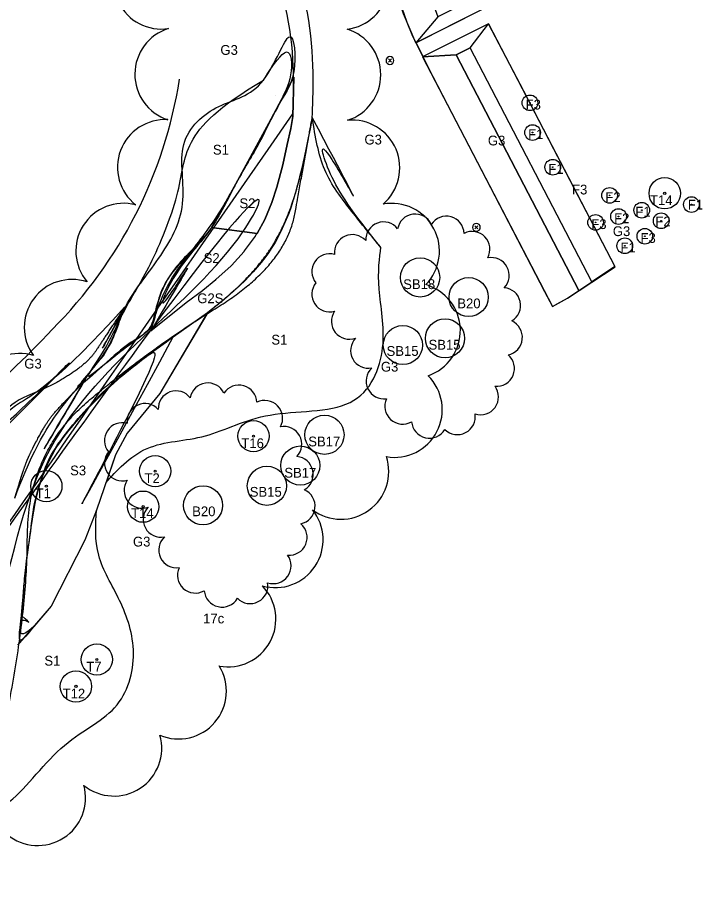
# Model space of a CAD drawing. Extents: x 0 to 512122, y 0 to 6212554.
# Drawn here: x 511674.6 to 511762.2, y 6211394.2 to 6211506.3 of the extents above; entities that cross this region are included whole.
import ezdxf

# ---------------------------------------------------------------- set-up
doc = ezdxf.new("R2010")
doc.units = 0
for name, color, linetype in [('_G3_engræsser', 7, 'Continuous'), ('_lights', 7, 'Continuous'), ('_ny fruit trees', 7, 'Continuous'), ('_Paths', 7, 'Continuous'), ('_S1_rabarber', 7, 'Continuous'), ('_S2_skovjorbær', 7, 'Continuous'), ('_S3_Mynte', 7, 'Continuous'), ('_S4_Løvstikke', 7, 'Continuous'), ('Clouds', 7, 'Continuous'), ('L40 jord udlagt muld og grøft', 7, 'Continuous'), ('Skel', 7, 'Continuous'), ('TV_U_AFM_Symbl_Gul', 7, 'Continuous'), ('TV_U_LYS_iWay', 7, 'Continuous'), ('TV_U_LYS_Mastenummer', 7, 'Continuous')]:
    doc.layers.add(name, color=color, linetype=linetype)

# ---------------------------------------------------------------- blocks, each defined once
blk = doc.blocks.new('SOLITAIRE TREES')
at = {"layer": 'Skel'}
for radius in [2, 0.141]:
    blk.add_circle((0, 0), radius, dxfattribs=at)

msp = doc.modelspace()

# ---------------------------------------------------------------- linework, layer by layer
at = {"layer": '_G3_engræsser'}
for centre, radius, start, end in [((511638.11, 6211507.41), 57.91, 315.0144, 351.0744), ((511598.66, 6211541.42), 109.92, 309.1647, 317.0116)]:
    msp.add_arc(centre, radius, start, end, dxfattribs=at)
at = {"layer": '_lights'}
for p, q in [((511722.42, 6211501), (511722.02, 6211500.61)), ((511722.02, 6211501), (511722.41, 6211500.6)), ((511733.47, 6211479.7), (511733.08, 6211479.31)), ((511733.08, 6211479.7), (511733.47, 6211479.3))]:
    msp.add_line(p, q, dxfattribs=at)
for centre, start, end in [((511722.22, 6211500.8), 315.5636, 315), ((511722.22, 6211500.8), 315, 315.5636), ((511733.27, 6211479.5), 315.5636, 315), ((511733.27, 6211479.5), 315, 315.5636)]:
    msp.add_arc(centre, 0.5, start, end, dxfattribs=at)
at = {"layer": '_ny fruit trees'}
for centre, radius in [((511740.12, 6211495.4), 1), ((511740.12, 6211495.4), 0.0426), ((511740.45, 6211491.61), 1), ((511740.45, 6211491.61), 0.0426), ((511743.03, 6211487.18), 1), ((511743.03, 6211487.18), 0.0426), ((511750.3, 6211483.58), 1), ((511750.3, 6211483.58), 0.0426), ((511760.76, 6211482.41), 1), ((511751.44, 6211480.88), 1), ((511754.41, 6211481.69), 1), ((511760.76, 6211482.41), 0.0426), ((511748.51, 6211480.13), 1), ((511751.44, 6211480.88), 0.0426), ((511754.41, 6211481.69), 0.0426), ((511756.89, 6211480.33), 1), ((511748.51, 6211480.13), 0.0426), ((511756.89, 6211480.33), 0.0426), ((511754.8, 6211478.36), 1), ((511754.8, 6211478.36), 0.0426), ((511752.24, 6211477.14), 1), ((511752.24, 6211477.14), 0.0426)]:
    msp.add_circle(centre, radius, dxfattribs=at)
at = {"layer": '_Paths'}
for points, degree in [([(511709.79, 6211493.65), (511709.91, 6211496.22), (511710.39, 6211506.9), (511703.25, 6211521.64), (511712.2, 6211531.87), (511715.7, 6211532.9), (511716.19, 6211533.02)], 3), ([(511712.29, 6211493.53), (511712.41, 6211496.11), (511712.92, 6211507.42), (511706.22, 6211521.24), (511713.56, 6211529.63), (511716.31, 6211530.48), (511716.67, 6211530.57)], 3), ([(511640.46, 6211394.16), (511666, 6211408.81), (511672.52, 6211429.48), (511676.56, 6211451.28), (511690.48, 6211465.66), (511705.08, 6211478.47), (511709.82, 6211494.01), (511640.46, 6211394.16), (511709.82, 6211494.01)], 3), ([(511651.32, 6211395.4), (511670.02, 6211402.1), (511675.84, 6211429.41), (511675.93, 6211450.77), (511691.5, 6211463.95), (511708.9, 6211474.67), (511711.29, 6211488), (511712.29, 6211493.57)], 2)]:
    msp.add_open_spline(points, degree=degree, dxfattribs=at)
at = {"layer": '_S1_rabarber'}
for points in [[(511698.93, 6211468.63), (511692.8, 6211458.27), (511688.64, 6211453.21), (511687.14, 6211450.42), (511685.93, 6211446.9)], [(511698.93, 6211468.63), (511692.8, 6211458.27), (511688.64, 6211453.21), (511687.14, 6211450.42), (511685.93, 6211446.9)], [(511698.91, 6211468.6), (511692.8, 6211458.27), (511688.64, 6211453.21), (511687.14, 6211450.42), (511685.93, 6211446.9)], [(511684.72, 6211443.38), (511684.72, 6211443.38), (511683.23, 6211439.53), (511678.91, 6211431.1), (511674.62, 6211426.15)], [(511684.72, 6211443.38), (511683.23, 6211439.53), (511678.91, 6211431.1), (511674.62, 6211426.15)]]:
    msp.add_lwpolyline(points, dxfattribs=at)
for points in [[(511706.05, 6211498.31), (511704.37, 6211496.16), (511700.27, 6211495.63), (511694.55, 6211490.67), (511696.74, 6211482.28), (511692.83, 6211475.35), (511687.76, 6211469.33), (511687.18, 6211464.39), (511680.03, 6211456.87), (511686.7, 6211462.87), (511689.02, 6211464.94), (511692.19, 6211466.4), (511692.26, 6211469.95), (511694.51, 6211474.61), (511699.59, 6211478.82), (511702.45, 6211485.35), (511705.77, 6211490.39), (511707.8, 6211495.3), (511710.48, 6211498.52), (511709.77, 6211506.87), (511707.62, 6211500.33), (511706.05, 6211498.31)], [(511706.05, 6211498.31), (511700.24, 6211494.87), (511695.7, 6211490.19), (511695.7, 6211484.27), (511691.41, 6211473.85), (511688.35, 6211469.4), (511686.09, 6211464.02), (511682.39, 6211459.13), (511686.22, 6211462.43), (511690.08, 6211465.38), (511691.7, 6211466.48), (511692.37, 6211468.99), (511694.34, 6211473.6), (511699.41, 6211479.52), (511702.53, 6211485.09), (511705.92, 6211491.08), (511708.18, 6211495.52), (511709.84, 6211498.66), (511709.53, 6211503.61), (511706.05, 6211498.31), (511706.05, 6211498.31), (511706.05, 6211498.31)], [(511712.29, 6211493.53), (511710.77, 6211485.59), (511708.57, 6211476.81), (511702.2, 6211471.1), (511698.93, 6211468.63)], [(511712.29, 6211493.53), (511710.77, 6211485.59), (511708.57, 6211476.81), (511702.2, 6211471.1), (511698.93, 6211468.63)], [(511721.06, 6211476.91), (511717.29, 6211481.6), (511714.18, 6211486.23), (511712.29, 6211493.53), (511721.06, 6211476.91), (511712.29, 6211493.53)], [(511721.06, 6211476.91), (511719.8, 6211478.46), (511717.38, 6211481.45), (511713.41, 6211486.6), (511712.7, 6211491), (511712.29, 6211493.53)], [(511698.91, 6211468.6), (511699.31, 6211468.96), (511699.65, 6211469.22), (511700.54, 6211469.93), (511701.09, 6211470.38), (511702.16, 6211471.31), (511702.68, 6211471.79), (511703.7, 6211472.78), (511704.2, 6211473.29), (511704.91, 6211474.09), (511705.15, 6211474.36), (511705.6, 6211474.91), (511705.82, 6211475.19), (511706.26, 6211475.76), (511706.47, 6211476.06), (511706.78, 6211476.5), (511706.88, 6211476.65), (511707.03, 6211476.88), (511707.08, 6211476.96), (511707.17, 6211477.11), (511707.22, 6211477.19), (511707.46, 6211477.57), (511707.64, 6211477.89), (511707.99, 6211478.52), (511708.16, 6211478.84), (511708.64, 6211479.81), (511708.93, 6211480.46), (511709.46, 6211481.8), (511709.7, 6211482.47), (511710.15, 6211483.83), (511710.35, 6211484.52), (511710.73, 6211485.9), (511710.9, 6211486.6), (511711.1, 6211487.5), (511711.3, 6211488.46), (511711.39, 6211488.94)], [(511685.93, 6211446.9), (511687.21, 6211448.33), (511690.71, 6211452.25), (511698.77, 6211452.14), (511706.01, 6211456.38), (511718.64, 6211455.51), (511722.16, 6211464.4), (511720.44, 6211471.89), (511720.89, 6211475.75), (511721.06, 6211476.91)], [(511685.93, 6211446.9), (511687.21, 6211448.33), (511690.71, 6211452.25), (511698.77, 6211452.14), (511706.01, 6211456.38), (511718.64, 6211455.51), (511722.16, 6211464.4), (511720.44, 6211471.89), (511720.89, 6211475.75), (511721.06, 6211476.91)], [(511685.93, 6211446.9), (511687.21, 6211448.33), (511690.71, 6211452.25), (511698.77, 6211452.14), (511706.01, 6211456.38), (511718.64, 6211455.51), (511722.16, 6211464.4), (511720.44, 6211471.89), (511720.89, 6211475.75), (511721.06, 6211476.91)], [(511659.81, 6211399.94), (511668.56, 6211404.36), (511673.2, 6211404.11), (511679.92, 6211414.02), (511688.01, 6211417.39), (511690.19, 6211425.29), (511687.87, 6211432.03), (511684.34, 6211437.49), (511684.6, 6211441.59), (511684.72, 6211443.38)], [(511659.81, 6211399.94), (511668.56, 6211404.36), (511673.2, 6211404.11), (511679.92, 6211414.02), (511688.01, 6211417.39), (511690.19, 6211425.29), (511687.87, 6211432.03), (511684.34, 6211437.49), (511684.6, 6211441.59), (511684.72, 6211443.38)]]:
    msp.add_open_spline(points, degree=3, dxfattribs=at)
at = {"layer": '_S2_skovjorbær'}
for p, q in [((511703.63, 6211476.5), (511705.02, 6211478.38)), ((511703.63, 6211476.5), (511705.02, 6211478.38)), ((511703.63, 6211476.5), (511705.02, 6211478.38)), ((511701.98, 6211474.63), (511703.57, 6211476.43)), ((511701.98, 6211474.63), (511703.57, 6211476.43)), ((511701.98, 6211474.63), (511703.57, 6211476.43)), ((511699.99, 6211472.87), (511701.89, 6211474.54)), ((511699.99, 6211472.87), (511701.89, 6211474.54)), ((511699.99, 6211472.87), (511701.89, 6211474.54)), ((511698.31, 6211471.46), (511699.97, 6211472.85)), ((511698.31, 6211471.46), (511699.97, 6211472.85)), ((511698.31, 6211471.46), (511699.97, 6211472.85))]:
    msp.add_line(p, q, dxfattribs=at)
for points in [[(511705.24, 6211478.7), (511699.42, 6211479.47), (511702.54, 6211485.04), (511709.92, 6211498.68), (511709.79, 6211493.65), (511709.54, 6211492.14), (511709.08, 6211490.07), (511708.52, 6211487.49), (511707.78, 6211484.62), (511707.14, 6211482.68), (511706.21, 6211480.5), (511705.24, 6211478.7)], [(511705.24, 6211478.7), (511699.42, 6211479.47), (511702.54, 6211485.04), (511709.92, 6211498.68), (511709.79, 6211493.65), (511709.54, 6211492.14), (511709.08, 6211490.07), (511708.52, 6211487.49), (511707.78, 6211484.62), (511707.14, 6211482.68), (511706.21, 6211480.5), (511705.24, 6211478.7)], [(511705.14, 6211478.6), (511705.21, 6211478.7), (511699.42, 6211479.47)], [(511705.14, 6211478.6), (511705.21, 6211478.7), (511699.42, 6211479.47)], [(511705.14, 6211478.6), (511705.21, 6211478.7), (511699.42, 6211479.47)], [(511691.67, 6211466.29), (511696.19, 6211469.89), (511698.26, 6211471.42)], [(511691.67, 6211466.29), (511696.19, 6211469.89), (511698.26, 6211471.42)], [(511691.67, 6211466.29), (511696.19, 6211469.89), (511698.26, 6211471.42)]]:
    msp.add_lwpolyline(points, dxfattribs=at)
msp.add_lwpolyline([(511706.21, 6211480.5), (511707.14, 6211482.68), (511707.78, 6211484.62), (511708.52, 6211487.49), (511709.08, 6211490.07), (511709.54, 6211492.14), (511709.79, 6211493.65), (511709.92, 6211498.68), (511702.54, 6211485.04), (511699.42, 6211479.47), (511705.24, 6211478.7)], close=True, dxfattribs=at)
for centre, radius, start, end in [((511704.34, 6211478.88), 0.85, 323.4908, 340.3298), ((511704.34, 6211478.88), 0.85, 323.4908, 340.3298), ((511704.34, 6211478.88), 0.85, 323.4908, 340.3298), ((511702.82, 6211477.09), 1, 318.5109, 323.4908), ((511702.82, 6211477.09), 1, 318.5109, 323.4908), ((511702.82, 6211477.09), 1, 318.5109, 323.4908), ((511701.23, 6211475.29), 1, 311.2445, 318.5109), ((511701.23, 6211475.29), 1, 311.2445, 318.5109), ((511701.23, 6211475.29), 1, 311.2445, 318.5109), ((511699.33, 6211473.62), 1, 310.0415, 311.2445), ((511699.33, 6211473.62), 1, 310.0415, 311.2445), ((511699.33, 6211473.62), 1, 310.0415, 311.2445), ((511697.67, 6211472.22), 1, 306.5138, 310.0415), ((511697.67, 6211472.22), 1, 306.5138, 310.0415), ((511697.67, 6211472.22), 1, 306.5138, 310.0415)]:
    msp.add_arc(centre, radius, start, end, dxfattribs=at)
for points in [[(511699.42, 6211479.47), (511697.51, 6211476.99), (511694.06, 6211473.15), (511691.67, 6211466.29), (511699.42, 6211479.47), (511691.67, 6211466.29)], [(511699.42, 6211479.47), (511697.51, 6211476.99), (511694.06, 6211473.15), (511691.67, 6211466.29), (511699.42, 6211479.47), (511691.67, 6211466.29)], [(511699.42, 6211479.47), (511698.81, 6211478.63), (511697.2, 6211476.39), (511693.09, 6211472.94), (511692.19, 6211468.74), (511691.67, 6211466.29)]]:
    msp.add_open_spline(points, degree=3, dxfattribs=at)
at = {"layer": '_S3_Mynte'}
msp.add_lwpolyline([(511694.53, 6211465.5), (511698.91, 6211468.6), (511692.8, 6211458.27), (511688.64, 6211453.21), (511687.14, 6211450.42), (511684.72, 6211443.38), (511683.23, 6211439.53), (511678.91, 6211431.1), (511676.69, 6211428.53)], dxfattribs=at)
msp.add_lwpolyline([(511694.53, 6211465.5), (511698.91, 6211468.6), (511692.8, 6211458.27), (511688.64, 6211453.21), (511687.14, 6211450.42), (511684.72, 6211443.38), (511683.23, 6211439.53), (511678.91, 6211431.1), (511676.69, 6211428.53)], dxfattribs=at)
for points in [[(511675.11, 6211429.93), (511675.26, 6211431.43), (511675.43, 6211433.5), (511675.74, 6211436.7), (511676.19, 6211439.93), (511676.86, 6211444.5), (511677.63, 6211447.3), (511678.99, 6211450.53), (511680.7, 6211453.03), (511683.58, 6211456.41), (511687.43, 6211460.16), (511691.16, 6211463.08), (511694.53, 6211465.5), (511675.11, 6211429.93), (511694.53, 6211465.5)], [(511675.11, 6211429.93), (511675.16, 6211430.43), (511675.29, 6211431.62), (511675.45, 6211433.88), (511675.71, 6211436.72), (511676.29, 6211440.37), (511676.64, 6211443.96), (511677.64, 6211447.51), (511678.8, 6211450.46), (511680.95, 6211453.44), (511683.74, 6211456.68), (511687.2, 6211460.1), (511690.99, 6211462.98), (511693.4, 6211464.7), (511694.53, 6211465.5)], [(511676.69, 6211428.53), (511675.92, 6211427.55), (511674.64, 6211425.91), (511674.98, 6211428.55), (511675.07, 6211429.48), (511675.11, 6211429.93)], [(511676.69, 6211428.53), (511674.93, 6211426.87), (511674.96, 6211428.47), (511675.11, 6211429.93), (511676.69, 6211428.53), (511675.11, 6211429.93)]]:
    msp.add_open_spline(points, degree=3, dxfattribs=at)
at = {"layer": '_S4_Løvstikke'}
for points, degree in [([(511688.33, 6211469.33), (511679.63, 6211459.7), (511674.05, 6211456.91), (511671.46, 6211454.05), (511670.68, 6211451.52), (511688.33, 6211469.33), (511670.68, 6211451.52)], 3), ([(511688.28, 6211469.25), (511685.8, 6211465.49), (511683.31, 6211461.75), (511679.63, 6211459.7)], 2), ([(511683.58, 6211460.56), (511684.79, 6211462.18), (511685.56, 6211462.99), (511685.75, 6211463.29), (511685.91, 6211463.71), (511686.28, 6211464.27), (511686.72, 6211464.98), (511687.17, 6211466.22), (511687.64, 6211467.57), (511688.33, 6211469.33), (511683.58, 6211460.56), (511688.33, 6211469.33)], 3), ([(511687.39, 6211466.89), (511687.58, 6211467.42), (511687.75, 6211467.93), (511687.93, 6211468.42)], 2), ([(511687.93, 6211468.42), (511688.04, 6211468.7), (511688.15, 6211468.98), (511688.28, 6211469.25)], 2), ([(511686.98, 6211465.8), (511687.01, 6211465.89), (511687.05, 6211465.98), (511687.09, 6211466.08)], 2), ([(511687.09, 6211466.08), (511687.16, 6211466.26), (511687.23, 6211466.44), (511687.29, 6211466.62)], 2), ([(511687.29, 6211466.62), (511687.33, 6211466.71), (511687.36, 6211466.8), (511687.39, 6211466.89)], 2), ([(511686.58, 6211464.93), (511686.73, 6211465.23), (511686.86, 6211465.52), (511686.98, 6211465.8)], 2), ([(511685.88, 6211463.69), (511685.95, 6211463.8), (511686.02, 6211463.91), (511686.09, 6211464.02)], 2), ([(511686.09, 6211464.02), (511686.27, 6211464.33), (511686.44, 6211464.64), (511686.58, 6211464.93)], 2), ([(511684.95, 6211462.35), (511685.2, 6211462.68), (511685.44, 6211463.02), (511685.66, 6211463.36)], 2), ([(511685.66, 6211463.36), (511685.74, 6211463.47), (511685.81, 6211463.58), (511685.88, 6211463.69)], 2), ([(511683.71, 6211460.75), (511684.04, 6211461.25), (511684.38, 6211461.75), (511684.79, 6211462.18)], 2), ([(511684.79, 6211462.18), (511684.84, 6211462.22), (511684.88, 6211462.27), (511684.93, 6211462.31)], 2), ([(511684.93, 6211462.31), (511684.94, 6211462.32), (511684.94, 6211462.33), (511684.95, 6211462.35)], 2), ([(511674.26, 6211444.91), (511676.69, 6211451.49), (511680.72, 6211457.31), (511683.18, 6211459.96), (511683.58, 6211460.56), (511674.26, 6211444.91), (511683.58, 6211460.56)], 3), ([(511682.63, 6211459.46), (511682.87, 6211459.75), (511683.26, 6211460.2), (511683.71, 6211460.75)], 2), ([(511679.63, 6211459.7), (511677.85, 6211458.7), (511674.52, 6211457.74), (511671.37, 6211454.53), (511670.88, 6211452.39), (511670.68, 6211451.52)], 3), ([(511682.68, 6211459.37), (511682.54, 6211459.25), (511682.45, 6211459.17), (511682.41, 6211459.14)], 2), ([(511682.45, 6211459.07), (511682.59, 6211459.22), (511682.72, 6211459.37), (511682.85, 6211459.53)], 2), ([(511682.53, 6211459.33), (511682.56, 6211459.37), (511682.59, 6211459.41), (511682.63, 6211459.46)], 2), ([(511682.85, 6211459.53), (511682.79, 6211459.47), (511682.73, 6211459.42), (511682.68, 6211459.37)], 2), ([(511681.27, 6211457.86), (511681.65, 6211458.27), (511682.05, 6211458.67), (511682.45, 6211459.07)], 2), ([(511682.39, 6211459.13), (511682.38, 6211459.14), (511682.39, 6211459.15), (511682.4, 6211459.16)], 2), ([(511682.41, 6211459.14), (511682.4, 6211459.13), (511682.39, 6211459.13), (511682.39, 6211459.13)], 2), ([(511682.4, 6211459.16), (511682.42, 6211459.19), (511682.46, 6211459.25), (511682.53, 6211459.33)], 2), ([(511677.07, 6211452.25), (511678.05, 6211454.09), (511679.27, 6211455.8), (511680.72, 6211457.31)], 2), ([(511680.72, 6211457.31), (511680.9, 6211457.49), (511681.08, 6211457.67), (511681.27, 6211457.86)], 2), ([(511676.56, 6211451.28), (511676.7, 6211451.57), (511676.85, 6211451.85), (511677, 6211452.13)], 2), ([(511677, 6211452.13), (511677.03, 6211452.17), (511677.05, 6211452.21), (511677.07, 6211452.25)], 2), ([(511675.34, 6211448.35), (511675.68, 6211449.35), (511676.09, 6211450.33), (511676.56, 6211451.28)], 2), ([(511675.01, 6211447.33), (511675.11, 6211447.67), (511675.22, 6211448.01), (511675.34, 6211448.35)], 2), ([(511674.79, 6211446.58), (511674.86, 6211446.83), (511674.93, 6211447.08), (511675.01, 6211447.33)], 2), ([(511674.26, 6211444.91), (511674.44, 6211445.47), (511674.61, 6211446.02), (511674.79, 6211446.58)], 2)]:
    msp.add_open_spline(points, degree=degree, dxfattribs=at)
at = {"layer": 'Clouds'}
for centre, radius, start, end in [((511715.99, 6211510.86), 6.1, 277.3369, 62.3369), ((511693.01, 6211510.92), 6.1, 133.6048, 278.6048), ((511695.71, 6211499.05), 6.1, 107.0668, 252.0668), ((511714.95, 6211498.98), 6.1, 287.6654, 72.6654), ((511693.49, 6211487.16), 6.1, 86.7882, 231.7882), ((511717.38, 6211487.1), 6.1, 310.4337, 95.4337), ((511688.17, 6211476.47), 6.1, 75.2403, 220.2403), ((511722.45, 6211476.46), 6.1, 315.4622, 100.4622), ((511725.45, 6211478.91), 2.28, 25.2077, 170.2077), ((511729.42, 6211478.64), 2.28, 2.0157, 147.0157), ((511721.4, 6211477.91), 2.28, 37.6761, 182.6761), ((511717.41, 6211476.29), 2.28, 41.3523, 186.3523), ((511732.72, 6211476.69), 2.28, 331.608, 116.608), ((511714.52, 6211473.85), 2.28, 74.1952, 219.1952), ((511735.18, 6211473.36), 2.28, 316.3178, 101.3178), ((511681.57, 6211466.74), 6.1, 71.4274, 216.4274), ((511714.52, 6211470.97), 2.28, 140.8408, 285.8408), ((511725.12, 6211466.31), 6.1, 289.0782, 74.0782), ((511736.64, 6211469.52), 2.28, 300.1916, 85.1916), ((511717.02, 6211467.49), 2.28, 145.6596, 290.6596), ((511736.87, 6211465.45), 2.28, 281.4375, 66.4375), ((511719.47, 6211463.77), 2.28, 135.9748, 280.9748), ((511674.86, 6211457.29), 6.1, 72.8126, 217.8126), ((511735.85, 6211461.47), 2.28, 264.8625, 49.8625), ((511721.46, 6211459.86), 2.28, 133.096, 278.096), ((511722.81, 6211456.22), 6.1, 260.1447, 45.1447), ((511698.94, 6211457.34), 2.28, 25.2077, 170.2077), ((511702.92, 6211457.07), 2.28, 2.0157, 147.0157), ((511694.89, 6211456.33), 2.28, 37.6761, 182.6761), ((511733.82, 6211457.84), 2.28, 251.5454, 36.5454), ((511706.22, 6211455.11), 2.28, 331.608, 116.608), ((511723.85, 6211456.64), 2.28, 154.9974, 299.9974), ((511690.9, 6211454.72), 2.28, 41.3523, 186.3523), ((511730.85, 6211455.3), 2.28, 224.7551, 9.7551), ((511688.01, 6211452.27), 2.28, 74.1952, 219.1952), ((511708.67, 6211451.79), 2.28, 316.3178, 101.3178), ((511727.26, 6211454.85), 2.28, 184.528, 329.528), ((511688.01, 6211449.39), 2.28, 140.8408, 285.8408), ((511710.13, 6211447.94), 2.28, 300.1916, 85.1916), ((511715.97, 6211448.31), 6.1, 233.2004, 18.2004), ((511690.52, 6211445.91), 2.28, 145.6596, 290.6596), ((511710.37, 6211443.88), 2.28, 281.4375, 66.4375), ((511692.96, 6211442.19), 2.28, 135.9748, 280.9748), ((511707.58, 6211439.58), 6.1, 254.071, 39.071), ((511709.35, 6211439.9), 2.28, 264.8625, 49.8625), ((511694.95, 6211438.29), 2.28, 133.096, 278.096), ((511707.31, 6211436.27), 2.28, 251.5454, 36.5454), ((511697.34, 6211435.06), 2.28, 154.9974, 299.9974), ((511701.54, 6211429.46), 6.1, 259.1824, 44.1824), ((511704.34, 6211433.72), 2.28, 224.7551, 9.7551), ((511700.76, 6211433.27), 2.28, 184.528, 329.528), ((511695.21, 6211420.25), 6.1, 246.8826, 31.8826), ((511686.95, 6211412.96), 6.1, 230.9058, 15.9058), ((511677.21, 6211406.64), 6.1, 230.1332, 15.1332)]:
    msp.add_arc(centre, radius, start, end, dxfattribs=at)
at = {"layer": 'L40 jord udlagt muld og grøft'}
for points in [[(511719.84, 6211532.64), (511724, 6211531.81), (511724.74, 6211524.88), (511725.4, 6211516.61), (511726.74, 6211510.85), (511728.35, 6211506.39), (511725.51, 6211503.06), (511723.96, 6211506.78), (511722.52, 6211511.27), (511721.38, 6211516.76), (511720.92, 6211521.34), (511720.67, 6211526.89), (511720.3, 6211530.04), (511719.84, 6211532.64)], [(511723.4, 6211508.54), (511724.37, 6211505.7), (511725.03, 6211504.14), (511727.06, 6211500), (511729.53, 6211495.25), (511735.07, 6211484.6), (511741.98, 6211471.32), (511742.99, 6211469.39), (511743.97, 6211469.93), (511744.93, 6211470.46), (511750.99, 6211474.45), (511743.16, 6211489.5), (511739.32, 6211496.88), (511734.83, 6211505.51), (511726.47, 6211501.3), (511725.59, 6211503.1), (511733.95, 6211507.31)], [(511732.49, 6211502.43), (511734.83, 6211505.51), (511750.97, 6211474.49), (511748.04, 6211472.54), (511732.49, 6211502.43)], [(511726.4, 6211501.27), (511742.99, 6211469.39), (511744.93, 6211470.46), (511746.37, 6211471.42), (511730.7, 6211501.53), (511726.4, 6211501.27)]]:
    msp.add_lwpolyline(points, dxfattribs=at)
for points in [[(511725.51, 6211503.06), (511733.95, 6211507.31), (511730.13, 6211507.29), (511728.35, 6211506.39)], [(511726.4, 6211501.27), (511730.7, 6211501.53), (511732.49, 6211502.43), (511734.83, 6211505.51)], [(511730.7, 6211501.53), (511746.37, 6211471.42), (511748.04, 6211472.54), (511732.49, 6211502.43)]]:
    msp.add_lwpolyline(points, close=True, dxfattribs=at)
at = {"layer": 'TV_U_LYS_iWay'}
msp.add_arc((511709.92, 6211499.22), 3.69, 232.0045, 232.0219, dxfattribs=at)
at = {"layer": 'TV_U_LYS_Mastenummer'}
for centre in [(511726.08, 6211473.1), (511732.28, 6211470.59), (511732.28, 6211470.59), (511729.26, 6211465.32), (511723.87, 6211464.46), (511713.85, 6211453), (511713.85, 6211453), (511710.76, 6211449.07), (511710.76, 6211449.07), (511706.49, 6211446.49), (511706.49, 6211446.49), (511698.33, 6211443.99)]:
    msp.add_circle(centre, 2.5, dxfattribs=at)

# ---------------------------------------------------------------- block references
at = {"layer": 'Skel'}
for p in [(511757.34, 6211483.85), (511704.78, 6211452.83), (511692.21, 6211448.36), (511678.3, 6211446.44), (511690.67, 6211443.82), (511684.76, 6211424.3), (511682.08, 6211420.86)]:
    msp.add_blockref('SOLITAIRE TREES', p, dxfattribs=at)

# ---------------------------------------------------------------- texts
at = {"layer": 'TV_U_AFM_Symbl_Gul'}
for s, p in [('G3', (511700.55, 6211501.53)), ('F3', (511739.57, 6211494.55)), ('F1', (511739.89, 6211490.76)), ('G3', (511718.96, 6211490.08)), ('G3', (511734.74, 6211489.96)), ('S1', (511699.59, 6211488.79)), ('F1', (511742.47, 6211486.33)), ('F3', (511745.5, 6211483.7)), ('S2', (511702.98, 6211481.95)), ('F2', (511749.75, 6211482.73)), ('T14', (511755.46, 6211482.33)), ('F1', (511760.3, 6211481.77)), ('F1', (511753.58, 6211480.87)), ('F2', (511750.88, 6211480.03)), ('F2', (511756.15, 6211479.62)), ('F3', (511747.96, 6211479.28)), ('G3', (511750.71, 6211478.38)), ('F3', (511754.25, 6211477.51)), ('F1', (511751.69, 6211476.29)), ('S2', (511698.41, 6211474.95)), ('SB18', (511723.91, 6211471.61)), ('G2S', (511697.59, 6211469.81)), ('B20', (511730.83, 6211469.16)), ('S1', (511707.06, 6211464.52)), ('SB15', (511727.15, 6211463.88)), ('SB15', (511721.79, 6211463.08)), ('G3', (511675.48, 6211461.46)), ('G3', (511721.06, 6211461.07)), ('SB17', (511711.78, 6211451.52)), ('T16', (511703.23, 6211451.3)), ('S3', (511681.34, 6211447.82)), ('SB17', (511708.72, 6211447.53)), ('T2', (511690.85, 6211446.83)), ('T1', (511676.94, 6211444.9)), ('SB15', (511704.3, 6211445.09)), ('B20', (511696.94, 6211442.6)), ('T14', (511689.14, 6211442.36)), ('G3', (511689.37, 6211438.73)), ('17c', (511698.34, 6211428.91)), ('S1', (511678.05, 6211423.52)), ('T7', (511683.4, 6211422.76)), ('T12', (511680.38, 6211419.32))]:
    msp.add_text(s, height=1.25, dxfattribs=at).set_placement(p)

doc.saveas('drawing.dxf')
